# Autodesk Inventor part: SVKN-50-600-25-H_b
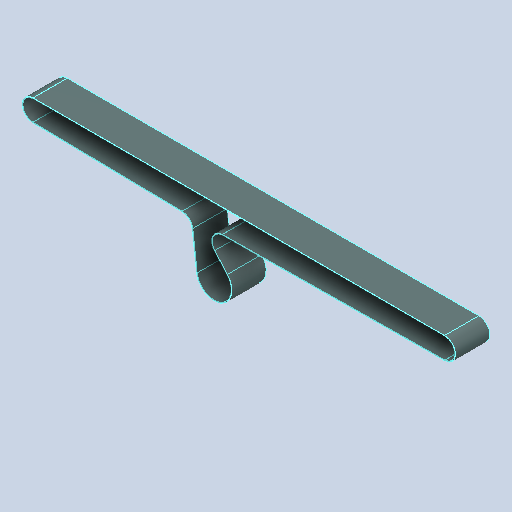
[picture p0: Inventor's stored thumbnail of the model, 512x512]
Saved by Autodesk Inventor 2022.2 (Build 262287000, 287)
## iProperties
Created: 2024-10
Part Number: SVKN-50-600-25-H_b
Material: Generico
Document SubType Name: Modeling
Designer: 18907419
Density: 1 g/cm^3
Appearance: Default
Author: 18907419
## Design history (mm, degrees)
feature "Solido1"
node "Solido2"
